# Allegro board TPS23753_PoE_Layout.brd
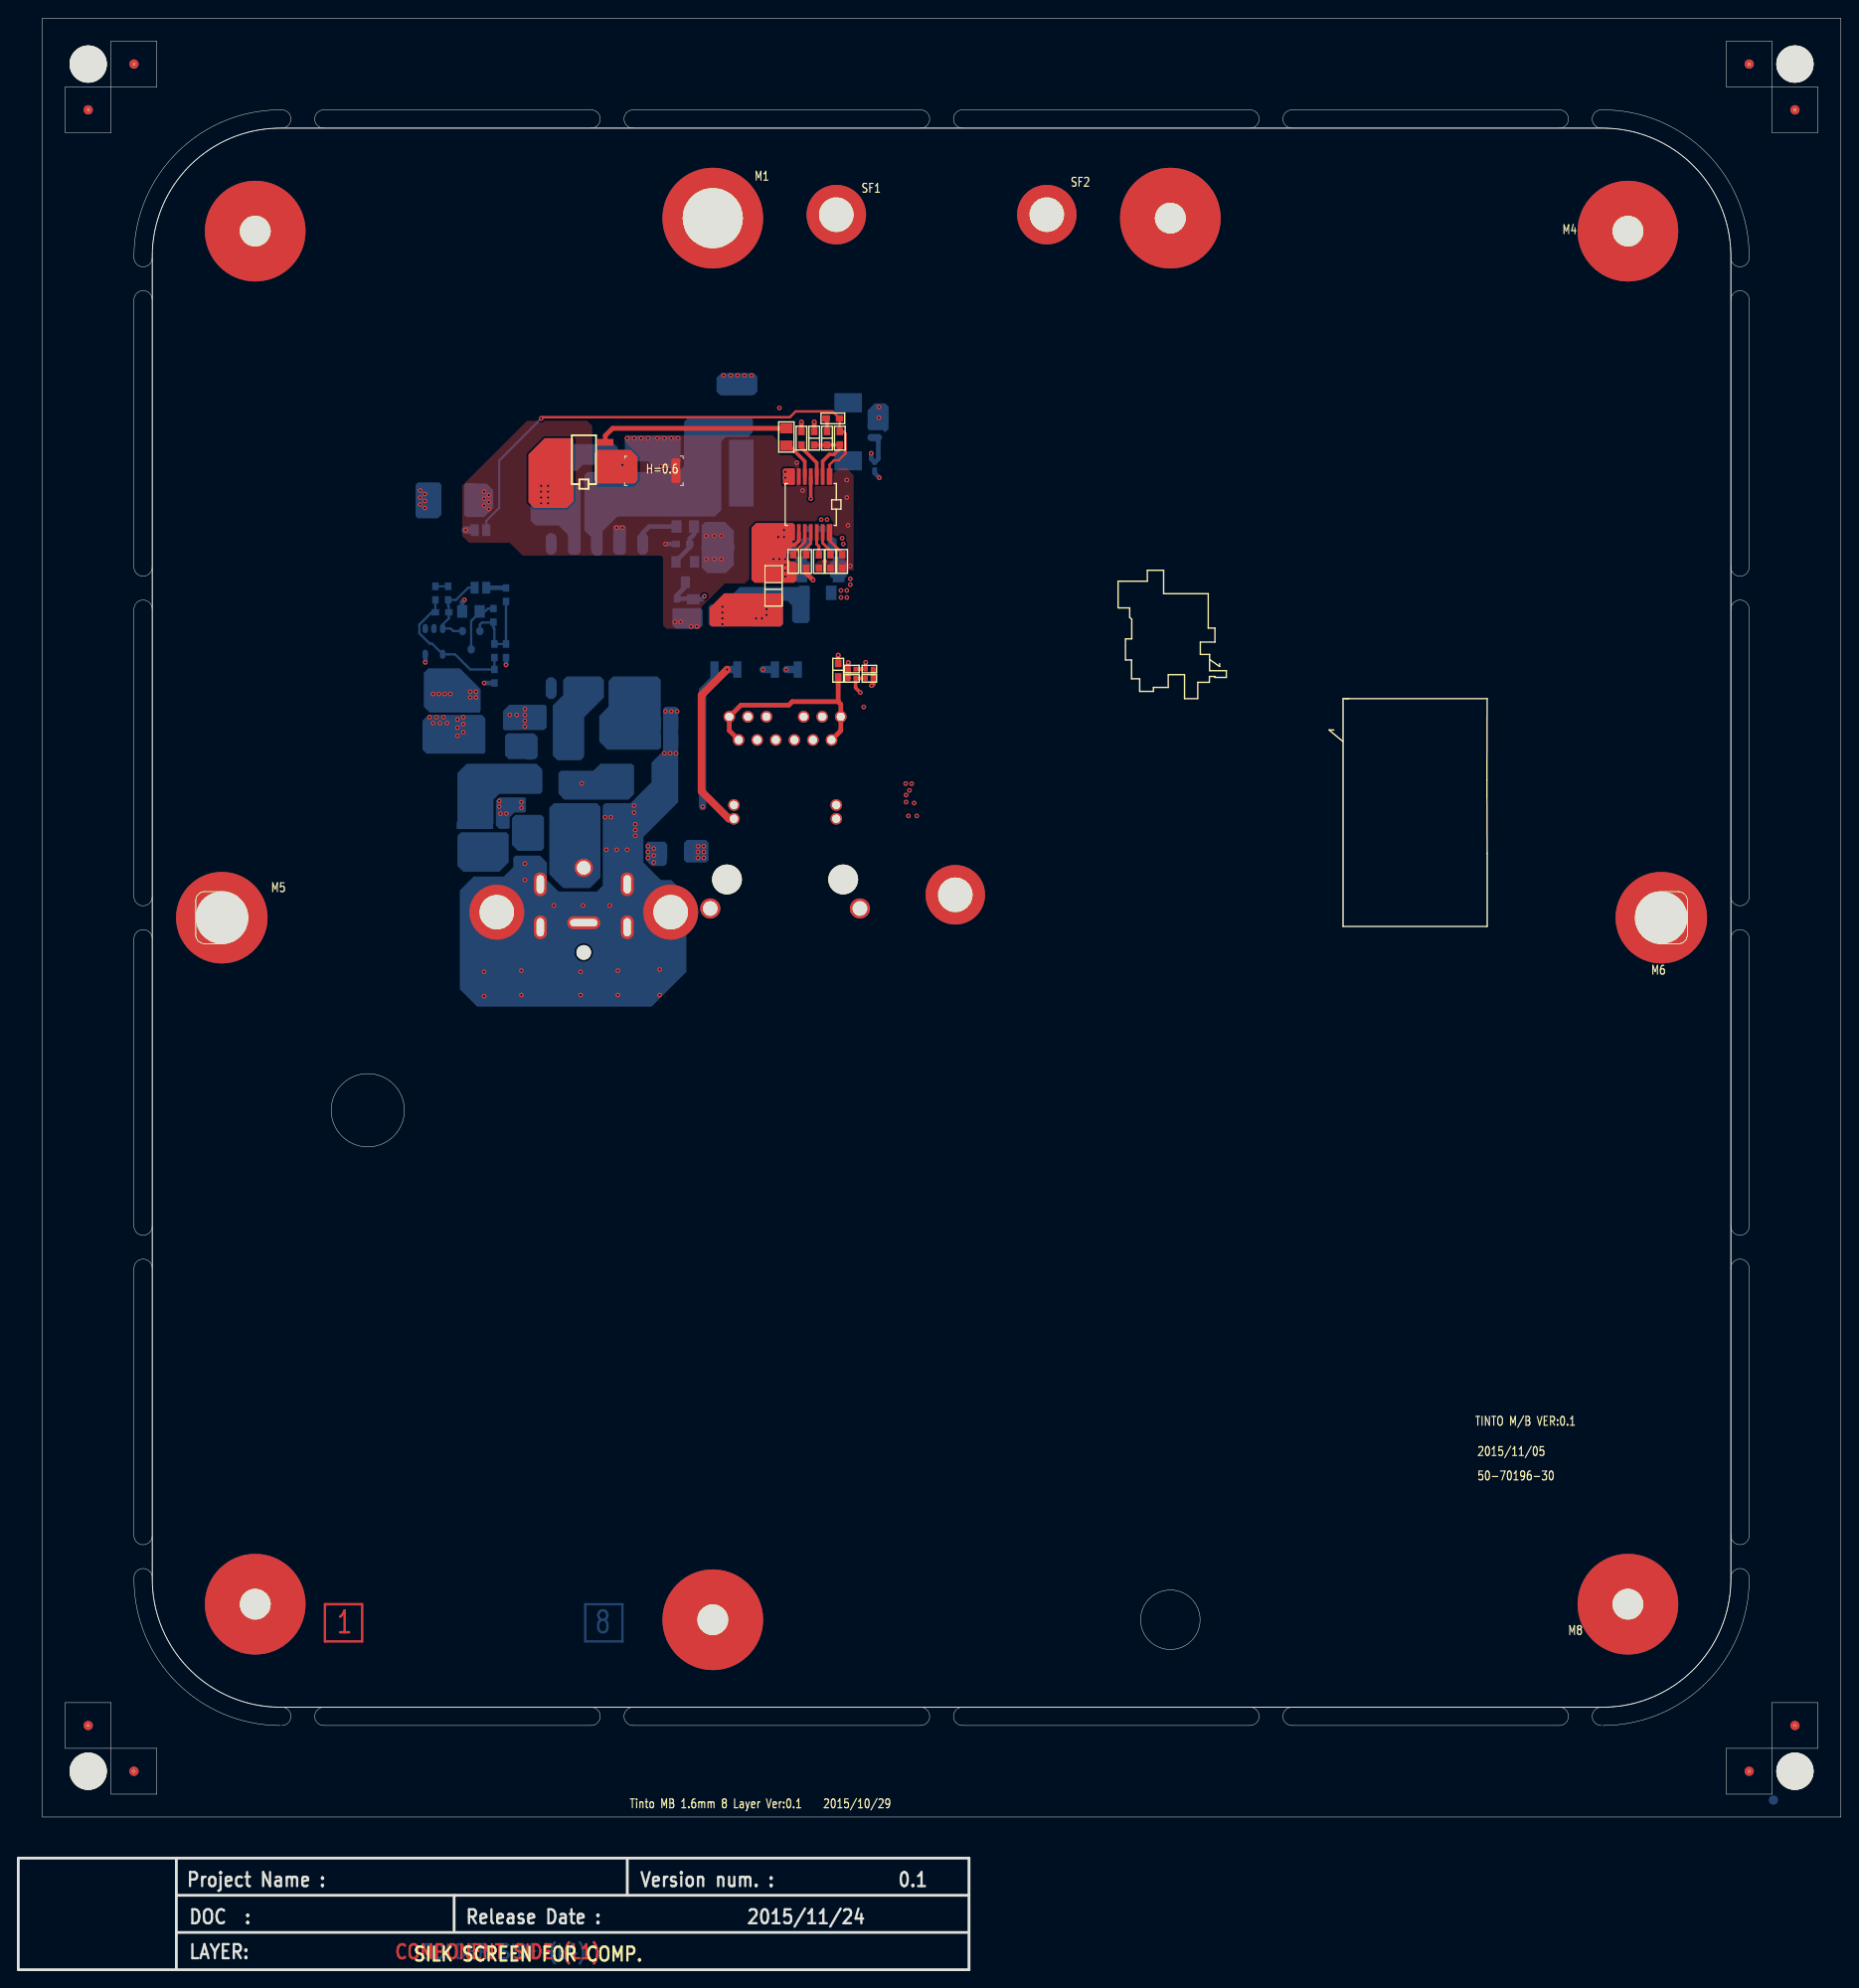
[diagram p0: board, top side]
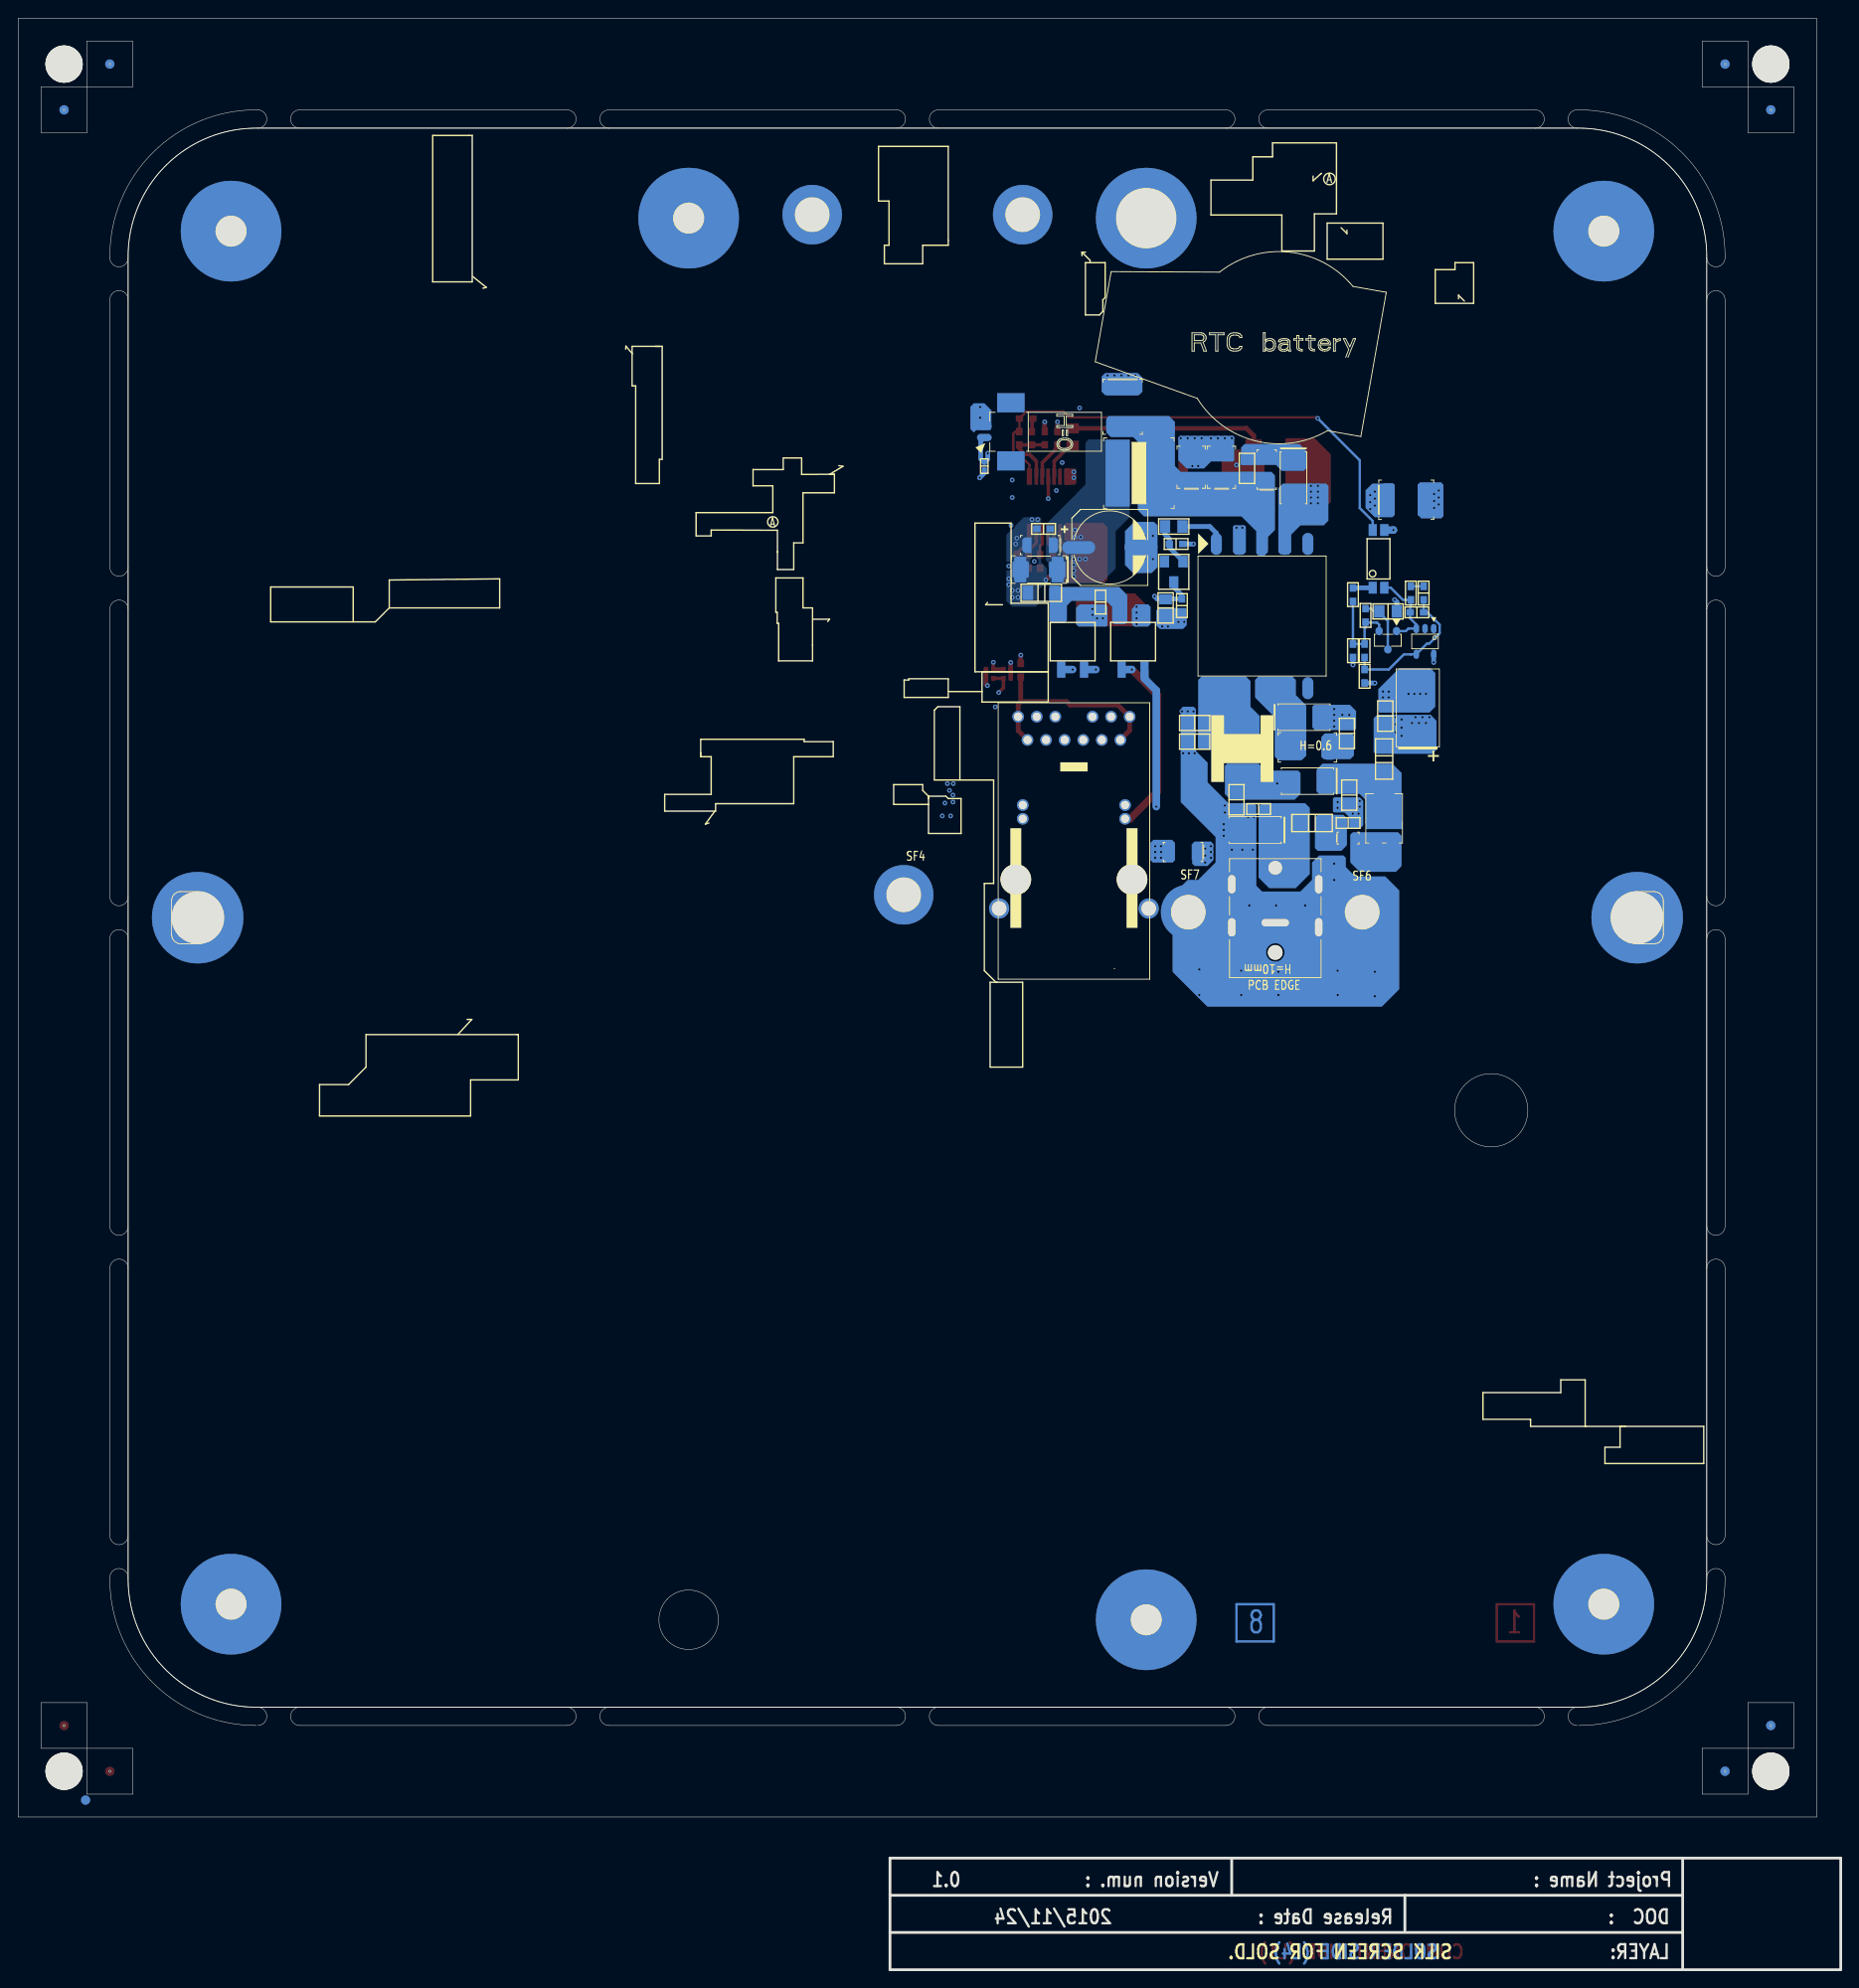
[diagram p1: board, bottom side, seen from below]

Outline 199.14 x 213.18 mm; copper layers: TOP, GND1, IN1, VCC1, VCC2, IN2, GND2, BOTTOM. Coordinates in mm from the lower left corner of the outline.
Outline path: circle c38.19,93.89 r4 ; circle c125.89,38.23 r3.25 ; 17.27,12.19 17.27,0 ; 17.27,8.13 103.89,8.13 ; 17.27,4.06 103.89,4.06 ; 47.62,8.13 47.62,4.32 ; 66.55,12.19 66.55,8.13 ; 0,12.19 0,0 103.89,0 103.89,12.19 0,12.19 ; 19.39,116.78 19.39,113.08 arc(19.68,112.37) 20.39,112.08 22.24,112.08 arc(25.09,114.93) 22.24,117.78 20.39,117.78 arc(19.68,117.49) 19.39,116.78 ; 179.54,112.08 arc(176.69,114.93) 179.54,117.78 181.39,117.78 arc(182.09,117.49) 182.39,116.78 182.39,113.08 arc(182.09,112.37) 181.39,112.08 179.54,112.08

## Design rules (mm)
constraint set DEFAULT: min track width 0.102
net group 50OHM-4(4.5): nets EMMC_CLK EMMC_CMD
net group GTX_CLK: nets GTX_CLK RGMII_TXCLK
net group LVDS1_CLK: nets LVDS1_CLK_N LVDS1_CLK_P
net group LVDS1_TX0: nets LVDS1_TX0_N LVDS1_TX0_P
net group LVDS1_TX1: nets LVDS1_TX1_N LVDS1_TX1_P
net group LVDS1_TX2: nets LVDS1_TX2_N LVDS1_TX2_P
net group LVDS1_TX3: nets LVDS1_TX3_N LVDS1_TX3_P
net group PHY_RST: nets PHY_RST RGMII_NRST
net group PHY_RX_CLK: nets PHY_RX_CLK RGMII_RXCLK
net group PWR-8: nets VDDHIGH_IN VDDHIGH_VPH
net group PWR-16: nets GEN_1V8 VGEN4_1V8
net group SD3_CLK: nets SD3_CLK SD_CLK_CN
net group SD3_CMD: nets SD3_CMD SD_CMD_CN
net group SD3_DATA0: nets SD3_DATA0 SD_DAT0_CN
net group SD3_DATA1: nets SD3_DATA1 SD_DAT1_CN
net group SD3_DATA2: nets SD3_DATA2 SD_DAT2_CN
net group SD3_DATA3: nets SD3_DATA3 SD_DAT3_CN
net group SD4_DA0: nets SD4_DA0 SD4_DATA0
net group SD4_DA1: nets SD4_DA1 SD4_DATA1
net group SD4_DA2: nets SD4_DA2 SD4_DATA2
net group SD4_DA3: nets SD4_DA3 SD4_DATA3
net group SD4_DA4: nets SD4_DA4 SD4_DATA4
net group SD4_DA5: nets SD4_DA5 SD4_DATA5
net group SD4_DA6: nets SD4_DA6 SD4_DATA6
net group SD4_DA7: nets SD4_DA7 SD4_DATA7
net group AUD3: nets AUD3_RXD AUD3_TXC AUD3_TXD AUD3_TXFS
net group CLK-20: nets CLK1_N CLK1_P CLK1_P_N CLK1_P_R
net group DDR_CLK: nets DRAM_SDCLK0 DRAM_SDCLK0_B DRAM_SDCLK1_B
net group DDR_CMD: nets DRAM_A0 DRAM_A1 DRAM_A2 DRAM_A3 DRAM_A4 DRAM_A5 DRAM_A6 DRAM_A7 DRAM_A8 DRAM_A9 DRAM_A10 DRAM_A11 DRAM_A12 DRAM_A13 DRAM_A14 DRAM_A15 DRAM_CAS_B DRAM_RAS_B DRAM_SDBA0 DRAM_SDBA1 DRAM_SDBA2 DRAM_WE_B
net group DDR_CTL: nets DRAM_CS0_B DRAM_CS1_B DRAM_SDCKE0 DRAM_SDCKE1 DRAM_SDODT0 DRAM_SDODT1
net group DDR_DATA0: nets DRAM_D0 DRAM_D4 DRAM_D7 DRAM_DQM0
net group DDR_DATA1: nets DRAM_D8 DRAM_D9 DRAM_D10 DRAM_D13 DRAM_DQM1
net group DDR_DATA2: nets DRAM_D16 DRAM_D17 DRAM_D20 DRAM_DQM2
net group DDR_DATA3: nets DRAM_D24 DRAM_D29 DRAM_DQM3
net group DDR_DQS: nets DRAM_SDQS0 DRAM_SDQS0_B DRAM_SDQS1 DRAM_SDQS1_B DRAM_SDQS2 DRAM_SDQS2_B DRAM_SDQS3 DRAM_SDQS3_B
net group DDR_OT: nets DRAM_RESET_B
net group EMMC_CLK: nets SD4_CLK
net group EMMC_CMD: nets SD4_CMD
net group GND: nets GND
net group I2C: nets I2C1_SCL I2C1_SDA I2C2_SCL I2C2_SDA I2C3_SCL I2C3_SDA PMIC_SCL PMIC_SDA
net group LVDS: nets LCD_CLK_N LCD_CLK_P LCD_TX0_N LCD_TX0_P LCD_TX1_N LCD_TX1_P LCD_TX2_N LCD_TX2_P LCD_TX3_N LCD_TX3_P
net group LVDS_3W-S11.4(12): nets LVDS0_CLK_N LVDS0_CLK_P LVDS0_TX0_N LVDS0_TX0_P LVDS0_TX1_N LVDS0_TX1_P LVDS0_TX2_N LVDS0_TX2_P LVDS0_TX3_N LVDS0_TX3_P
net group PWR: nets 2V5_RGMII 5VDDM DDR_1V5_L DDR_VREF DVDDL_RGMII EMMC_VDD ETH_RBIAS ETH_VDDIO_REG GEN_3V3_IN GEN_3V3_PMIC LAN_AVDD33 LAN_AVDDL LAN_DVDD_SW LCD_AVDD LCD_BL+ LCD_BL- LCD_PWM LCD_SUP LCD_VCOM LCD_VCOM_IN LCD_VDD LCD_VGH LCD_VGL LVDS_2V5 N2030210 N17702392 N18409851 N19092772 N19097147 N24036489 N24124655 N24230966 N24230987 N24253285 NFC_PVDD NFC_SIMVCC NFC_SVDD NFC_VBAT NVCC_CSI NVCC_EIM NVCC_MIPI NVCC_RGMII NVCC_SD1 NVCC_SD2 PCIE_VP PMIC_VCORE PMIC_VCOREREF PMIC_VDDOTP PMIC_VSNVS RTC_3V SATA_VP SENSOR_3V3 SENSOR_5V SET_1V8 SET_3V3 SW1CLX SYS_3V SYS_5V USB_H1_VBUS USB_OTG_VBUS VCCRTC VCOREDIG VDD5V_IN VDD_SNVS_CAP VDDCORE_R VDDSOC_R VGEN1_1V5 VGEN6_3V3 VOUT_1V8 VOUT_3V3 WLAN_3VIN
net group PWR-10: nets RF_ANT1 RF_ANT1_CN RF_ANT2 RF_ANT2_CN
net group PWR-12: nets NFC_1.8VDDM NFC_3VDDM NVCC_PLL_LDO NVCC_PLL_OUT
net group PWR-20: nets ETH_3V3 GEN_3V3 HDMI_VP N22820015 N24165639 N27686456 N27686764 NVCC_3V3 OTG_VBUS PA_3V3 VDD12V_POE VDD_IO VGEN2_1V5
net group PWR-40: nets AUX_3V15
net group PWR-80: nets VDDPU VDDSOC VDDSOC_CAP
net group PWR-100: nets DDR_1V5 VDD13_12 VDD_ARM_CAP VDDCORE
net group PWR-240: nets PMU3V
net group PWR-W6: nets GEN_2V5 HDMI_VPH PCIE_VPH SATA_VPH VGEN5_2V8 VSNVS_3V0
net group PWR-W32: nets PMIC_5V POE_VDD_CN POE_VSS_CN VDD_PSE_M1 VDD_PSE_M2 VDD_PSE_P1 VDD_PSE_P2
net group PWR_GATE: nets 3V_SW 5V_SW GEN_3V3_SW N17701522 N18409953 N39184104 N39184195 N39184527 N39184670 SW1LX SW3LX SW4LX SW_T
net group RGMII: nets RGMII_MDC RGMII_MDIO RGMII_RXD0 RGMII_RXD1 RGMII_RXD2 RGMII_RXD3 RGMII_RXDV RGMII_TXD0 RGMII_TXD1 RGMII_TXD2 RGMII_TXD3 RGMII_TXEN
net group S-10: nets G_LED_FB1 G_LED_FB2 G_LED_FB3 G_LED_FB4 G_LED_FB5 LED_G_POWER LED_GREEN LED_R_POWER LED_RED LED_YELLOW N17701582 N17701584 N17701586 N17701588 N17701590 N17701592 N17701594 N17701596 N17701598 N17701600 N17701602 N17701604 N17701700 N17701702 N17701704 N17701706 N17702195 N17702197 N17702222 N17702224 N17702236 N17702240 N17702242 N17702244 N17702269 N17702271 N17702317 N17702327 N17702414 N17702416 N17702418 N17702420 N17702422 N17702424 N17702426 N17702428 N17702430 N17702432 N17702434 N17702436 N17702438 N17702440 N17702495 N17702497 N17702499 N17702501 N17702503 N17702505 N17702507 N17702509 N17702511 N17702513 N17702515 N17702517 N17702581 N17702583 N17736265 N17736966 N17737669 N17738374 N17739081 N17739790 N17740501 N17741214 N17741929 N17742646 N17743365 N17744086 N17744809 N17745534 R_LED_IFB1 R_LED_IFB2 R_LED_IFB3 R_LED_IFB4 R_LED_IFB5 RGMII_LED_10_100 RGMII_LED_1000 RGMII_LED_ACT
net group S-20: nets N25586908 N28364944 N28380123
net group S_2W-S8(9): nets UART5_CTS UART5_RTS UART5_RXD UART5_TXD
net group SD: nets SD2_CD_B SD2_DATA4 SD2_DATA5 SD2_DATA6 SD2_DATA7 SD2_WP SD3_CD_B SD3_DATA4 SD3_DATA5 SD3_DATA6 SD3_DATA7 SD3_WP SD_CD#_CN
net group UART: nets UART1_RX UART1_RX_CN UART1_TX UART1_TX_CN UART3_RXD UART3_TXD
net group UART5: nets BT_CTS BT_RTS BT_RXD BT_TXD
net group USB: nets USB_HOST_DN USB_HOST_DP USB_OTG_DN USB_OTG_DP
net group XTAL: nets N27686566 N27686641 N27686643 N27686649 PHY_XTLI PHY_XTLO RTC_XTALI RTC_XTALO XTAL24_IN XTAL24_OUT

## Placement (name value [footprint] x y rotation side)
C27  -  [C0603]  86.97 167.31 90 top
C28  0.033uF  [C0603]  88.37 167.31 90 top
C49  2200pF  [C1812]  47.48 160.58 180 bottom
C153  0.1uF  [C0603]  89.59 141.96 270 top
C209  0.1UF  [C0402]  93.58 164.26 90 bottom
C233  2200pF  [C1812]  78.47 170.74 270 bottom
C248  -  [C1210]  67.67 164.13 0 bottom
C249  -  [C1210]  70.97 164.13 0 bottom
C250  -  [C1206]  62.72 163.88 0 bottom
C258  -  [CE_W830H830]  79.86 155.37 270 bottom
C259  -  [C0603]  72.62 155.75 180 bottom
C264  6800pF  [C0603]  45.57 150.39 270 bottom
C273  -  [C1206]  87.48 155.63 270 bottom
C275  0.22uF  [C0603]  71.99 149.02 270 bottom
C276  10pF  [C0603]  46.31 148.28 180 bottom
C278  -  [C0805]  73.77 148.77 270 bottom
C283  -  [C0805]  49.46 148.39 180 bottom
C288  -  [C0805]  70.59 136.19 0 bottom
C291  -  [C0805]  70.59 134.16 0 bottom
C292  -  [C0805]  53.95 135.05 90 bottom
C309  -  [C0805]  53.7 128.32 270 bottom
C313  -  [C0805]  66.02 127.81 270 bottom
C318  0.1uF  [C0603]  53.83 125.27 180 bottom
C320  -  [C7343]  46.21 137.85 90 bottom
C322  0.1uF  [C0603]  63.61 126.8 0 bottom
C323  -  [C0805]  49.76 136.96 90 bottom
C325  1000pF  [C1206]  71.86 122.1 270 bottom
C405  -  [C0603]  80.88 149.4 90 bottom
C406  -  [C0603]  87.1 157.4 0 bottom
CN2  -  [85204-0200]  93.58 167.38 270 bottom
CN3  -  [RJ45_16P_2PAD_RT5-3030T22Q]  83.79 119.1 0 bottom
CN5  -  [DCJACK_2DC-G213-B28]  61.79 114.38 0 bottom
D9  -  [DIODE_SMA]  59.8 162.99 270 bottom
D10  -  [SOT23_123]  72.88 152.7 270 bottom
D11  -  [DIODE_SMA-L]  87.61 152.96 0 bottom
D12  BAV99  [SOT_23-NPNP]  49.49 145.24 270 bottom
D13  -  [DIODE_SMA]  58.65 136.83 180 bottom
D14  -  [DIODE_MDI-H2_7]  77.32 145.08 90 bottom
D15  -  [DIODE_MDI-H2_7]  83.93 145.08 90 bottom
D16  -  [DIODE_SMA]  58.27 129.84 0 bottom
D17  -  [DIODE_POWERDI_3]  49.89 125.78 180 bottom
D18  -  [DIODE_SMA]  63.99 124.51 0 bottom
FB9  UPB321611T-121Y-N  [L1206]  82.53 151.18 90 top
FB10  UPB321611T-121Y-N  [L1206]  87.36 150.42 0 bottom
FB13  UPB321611T-121Y-N  [L1206]  57.76 125.27 180 bottom
FB14  UPB321611T-121Y-N  [L1206]  49.89 132.26 90 bottom
FS1  -  [PPTC0603]  53.83 123.62 90 bottom
L10  -  [L_CHOKE_670X670_CDRH6D28]  76.69 163.5 270 bottom
L12  -  [L_CHOKE_650X730-R185_350]  65.38 133.4 270 bottom
M1  -  [CTB1100Z700H650]  75.89 191.35 0 top
M2  -  [CTB1100Z380H330]  125.89 191.35 0 top
M3  -  [CTB1100Z380H330]  25.89 189.93 0 top
M4  -  [CTB1100Z380H330]  175.89 189.93 0 top
M5  -  [CTB1000Z620H570]  22.24 114.93 0 top
M6  -  [CTB1000Z620H570]  179.54 114.93 0 top
M7  -  [CTB1100Z380H330]  25.89 39.93 0 top
M8  -  [CTB1100Z380H330]  175.89 39.93 0 top
M10  -  [CTB1100Z380H330]  75.89 38.23 0 top
NOREF  -  []  25.89 39.93 0 top
NOREF#2  -  [unnamed#2]  7.64 21.68 0 top
NOREF#3  -  [unnamed#3]  7.64 203.18 0 top
NOREF#4  -  [unnamed#3]  12.64 21.68 0 top
NOREF#5  -  [unnamed#3]  7.64 26.68 0 top
NOREF#6  -  [unnamed#2]  194.14 21.68 0 top
NOREF#7  -  [unnamed#3]  194.14 203.18 0 top
NOREF#8  -  [unnamed#3]  25.89 39.93 0 top
NOREF#9  -  [unnamed#3]  12.64 208.18 0 top
NOREF#10  -  [unnamed#3]  189.14 208.18 0 top
NOREF#11  -  [unnamed#3]  189.14 21.68 0 top
NOREF#12  -  [unnamed#2]  194.14 208.18 0 top
NOREF#13  -  [unnamed#3]  194.14 26.68 0 top
NOREF#14  -  [unnamed#2]  7.64 208.18 0 top
NOREF#15  -  []  -0.13 -0.01 0 top
NOREF#16  -  [unnamed#3]  191.79 18.53 180 bottom
NOREF#17  -  [unnamed#3]  7.64 26.68 180 bottom
NOREF#18  -  [unnamed#3]  12.64 208.18 180 bottom
NOREF#19  -  [unnamed#3]  12.64 21.68 180 bottom
NOREF#20  -  [unnamed#3]  7.64 203.18 180 bottom
NOREF#21  -  [unnamed#3]  189.14 208.18 180 bottom
NOREF#22  -  [unnamed#3]  194.14 203.18 180 bottom
Q1  Si4848DY-T1  [SMD8A-184]  61.81 164.96 90 top
R10  1.5K  [R0603]  89.01 169.47 0 top
R11  -  [R0603]  85.58 167.31 270 top
R16  -  [R0805]  83.93 167.44 90 top
R17  2K  [R0603]  89.77 167.31 90 top
R20  0.39  [R2010]  69.45 163.75 0 top
R48  80.6K  [R0603]  88.75 153.85 270 top
R49  59K  [R0603]  90.02 153.85 270 top
R54  -  [R0603]  84.69 153.85 90 top
R55  -  [R0603]  86.09 153.85 90 top
R56  -  [R0603]  87.48 153.85 90 top
R92  10K  [R0402]  92.99 142.09 180 top
R93  10K  [R0402]  91.09 142.09 0 top
R94  10K  [R0402]  92.99 141.07 180 top
R96  10K  [R0402]  91.09 141.07 0 top
R172  -  [R0805]  64.88 164.01 90 bottom
R193  -  [R0805]  72.88 157.66 180 bottom
R208  -  [R0603]  46.97 150.39 90 bottom
R213  2K  [R0603]  53.3 150.21 90 bottom
R216  -  [R0603]  52.03 144.09 270 bottom
R217  -  [R0603]  53.3 144.09 90 bottom
R219  -  [R0603]  52.03 141.3 270 bottom
R236  -  [R0603]  51.92 147.95 90 bottom
R243  -  [R2010]  58.27 133.53 180 bottom
SF1  -  [NUT_CT650BZ410H370]  89.39 191.73 0 top
SF2  -  [NUT_CT650BZ410H370]  112.39 191.73 0 top
SF4  -  [NUT_CT650BZ410H370]  102.39 117.43 180 bottom
SF6  -  [NUT_CTB600Z420H370]  52.29 115.53 180 bottom
SF7  -  [NUT_CTB600Z420H370]  71.29 115.53 180 bottom
T1  -  [TRANSFOMER_10_W1400L1765P250]  63.23 147.88 0 bottom
U4  TPS23753PWR  [TSSOP14__65M_240-H1_2]  86.59 160.07 180 top
U22  TCMT1107  [SOP4_1_27M]  50.5 154.13 180 bottom
U25  TL431ACDBVR  [SOT_23_5-H1_45]  45.42 145.11 270 bottom

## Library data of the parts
C27 = 10-52868-00
C28 = 10-51208-00
C49 C233 = 10-51542-00
C153 C318 C322 = 10-52979-00
C209 = 10-53021-00
C248 C249 = 10-51642-00
C250 C273 = 10-51546-00
C258 = 10-30880-01
C259 C405 C406 = 10-51643-00
C264 = 10-51177-00
C275 = 10-52872-00
C276 = 10-51452-00
C278 = 10-51639-00
C283 C323 = 10-51372-00
C288 C291 C309 C313 = 10-51616-00
C292 = 10-51448-00
C320 = 10-40806-01
C325 = 10-51179-00
CN2 = 20-20294-20
CN3 = 20-26663-01
CN5 = 20-26641-01
D9 = 06-10840-02
D10 = 06-10588-02
D11 = 06-10836-01
D12 = 06-10571-05
D13 D16 = 06-10873-01
D14 D15 = 06-10963-01
D17 = 06-10944-01
D18 = 06-10961-01
FB9 FB10 FB13 FB14 = 21-92453-01
FS1 = 21-10724-02
L10 = 12-00911-01
L12 = 12-01952-02
M1 = CTB1100Z700H650
M2-M4 M7 M8 M10 = CTB1100Z380H330
M5 M6 = CTB1000Z620H570
Q1 = 06-24124-01
R10 = 11-14720-00
R11 = 11-14244-00
R16 R193 = 11-13582-00
R17 R213 = 11-14267-00
R20 = 11-13374-00
R48 = 11-14393-00
R49 = 11-13067-00
R54 = 11-14539-00
R55 = 11-12938-00
R56 R208 R236 = 11-14280-00
R92 R94 = NU_11-14297-00
R93 R96 = 11-14297-00
R172 = 11-13581-00
R216 = 11-13568-00
R217 = 11-14214-00
R219 = 11-13338-00
R243 = 11-13504-00
SF1 SF2 = 24-12459-00
SF4 = 24-12460-00
SF6 SF7 = 24-12194-00
T1 = 12-02504-01
U4 = 05-32472-01
U22 = 05-32471-01
U25 = 05-32473-01

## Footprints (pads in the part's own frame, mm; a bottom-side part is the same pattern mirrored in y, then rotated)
85204-0200
  oval 0.8x1.6 smd: 1(0,0) 2(-1.25,0)
  rect 2.1x3 smd: PAD1(2.55,2.9) PAD2(-3.8,2.9)
C0402
  rect 0.457x0.508 smd: 1(-0.4,0) 2(0.4,0)
C0603
  rect 0.813x0.711 smd: 1(-0.737,0) 2(0.737,0)
C0805
  rect 1.118x1.372 smd: 1(-0.95,0) 2(0.95,0)
C1206
  custom 0.25x0.25 smd: 1(0,1.45) 2(0,-1.45)
C1210
  custom 0.35x0.35 smd: 1(0,1.4) 2(0,-1.4)
C1812
  custom 0.35x0.35 smd: 1(-1.95,0) 2(1.95,0)
C7343
  custom 0.475x0.475 smd: 1(-3.1,0) 2(3.1,0)
CE_W830H830
  oval 1.4x3.6 smd: 1(0,-3.4) 2(0,3.4)
CTB1000Z620H570
  round 10 hole 5.7: 1(0,0)
CTB1100Z380H330
  round 11 hole 3.3: 1(0,0)
CTB1100Z700H650
  round 11 hole 6.5: 1(0,0)
DCJACK_2DC-G213-B28
  round 1.6 hole 1.6 unplated: (0,3.25)
  round 2 hole 1.5: 1(0,-6)
  oval 3.6x1.4 hole 3x0.8: 2(0,0)
  oval 1.4x2.6 hole 0.8x2: PAD1(-4.75,0.5) PAD2(4.75,0.5) PAD3(-4.75,-4.2) PAD4(4.75,-4.2)
DIODE_MDI-H2_7
  rect 1.803x0.889 smd: 1(3.048,-1.25) 2(3.048,1.25) 3(-3.048,1.25) 4(-3.048,-1.25)
DIODE_POWERDI_3
  custom 0.275x0.275 smd: A1(-0.92,-2.9) A2(0.92,-2.9)
  custom 1x1 smd: C(0,1.05)
DIODE_SMA
  rect 1.8x2.2 smd: A(1.95,0) C(-1.95,0)
DIODE_SMA-L
  custom 0.45x0.45 smd: A(2,0) C(-2,0)
L1206
  rect 1.168x1.575 smd: 1(-1.473,0) 2(1.473,0)
L_CHOKE_650X730-R185_350
  rect 1.85x3.5 smd: 1(-2.775,0) 2(2.775,0)
L_CHOKE_670X670_CDRH6D28
  rect 7.3x2.65 smd: 1(0,-2.325) 2(0,2.325)
NUT_CT650BZ410H370
  round 6.5 hole 3.7: 1(0,0)
NUT_CTB600Z420H370
  round 6 hole 3.7: 1(0,0)
PPTC0603
  custom 0.15x0.15 smd: 1(0,0.7) 2(0,-0.7)
R0402
  rect 0.457x0.508 smd: 1(-0.4,0) 2(0.4,0)
R0603
  rect 0.813x0.711 smd: 1(-0.737,0) 2(0.737,0)
R0805
  rect 1.118x1.372 smd: 1(-0.95,0) 2(0.95,0)
R2010
  custom 0.25x0.25 smd: 1(-2.4,0) 2(2.4,0)
RJ45_16P_2PAD_RT5-3030T22Q
  round 3.25 hole 3.25 unplated: (-6.35,0) (6.35,0)
  round 1.27 hole 0.9: 1(-5.075,-15.24) 2(-3.045,-15.24) 3(-1.015,-15.24) 4(1.015,-15.24) 5(3.045,-15.24) 6(5.075,-15.24) 7(-6.09,-17.78) 8(-4.06,-17.78) 9(-2.03,-17.78) 10(2.03,-17.78) 11(4.06,-17.78) 12(6.09,-17.78) 13(-5.59,-8.13) 14(5.59,-8.13) 15(-5.59,-6.63) 16(5.59,-6.63)
  round 2.2 hole 1.6: PAD1(-8.175,3.17) PAD2(8.175,3.17)
SMD8A-184
  rect 0.711x1.778 smd: 1(-1.905,-2.34) 2(-0.635,-2.34) 3(0.635,-2.34) 4(1.905,-2.34) 5(1.905,2.34) 6(0.635,2.34) 7(-0.635,2.34) 8(-1.905,2.34)
SOP4_1_27M
  rect 0.889x1.295 smd: 1(-0.635,-3.15) 2(0.635,-3.15) 3(0.635,3.15) 4(-0.635,3.15)
SOT23_123
  rect 1.27x1.016 smd: 1(-1.118,1.016) 2(-1.118,-1.016) 3(1.118,0)
SOT_23-NPNP
  oval 0.9x0.8 smd: N(-1,-0.95) NP(1,0) P(-1,0.95)
SOT_23_5-H1_45
  oval 1x0.6 smd: 1(-1.4,0.95) 2(-1.4,0) 3(-1.4,-0.95) 4(1.4,-0.95) 5(1.4,0.95)
TRANSFOMER_10_W1400L1765P250
  oval 1.2x2.4 smd: 1(5,-7.88) 2(2.5,-7.88) 3(0,-7.88) 4(-2.5,-7.88) 5(-5,-7.88) 6(-5,7.88) 7(-2.5,7.88) 8(0,7.88) 9(2.5,7.88) 10(5,7.88)
TSSOP14__65M_240-H1_2
  rect 0.61x1.778 smd: 1(-2.052,-3.048) 7(2.052,-3.048) 8(2.052,3.048) 14(-2.052,3.048)
  rect 0.406x1.778 smd: 2(-1.3,-3.048) 3(-0.65,-3.048) 4(0,-3.048) 5(0.65,-3.048) 6(1.3,-3.048) 9(1.3,3.048) 10(0.65,3.048) 11(0,3.048) 12(-0.65,3.048) 13(-1.3,3.048)
unnamed#2
  round 4.064 hole 4.064 unplated: (0,0)
unnamed#3
  round 1.016 smd: 1(0,0)

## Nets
2V5_RGMII: R92.1(TP-1) R94.1(TP-1)
GND: C49.2 C153.1(TP-1) C209.1(TP-1) C233.1 C283.2 C288.2 C291.2 C292.2 C309.2 C313.2 C318.2(TP-2) C320.2 C322.2(TP-2) C323.2 C325.1(TP-1) CN2.2 CN5.2 CN5.PAD1 CN5.PAD2 CN5.PAD3 CN5.PAD4 D13.A D18.A M1.1 M2.1 M3.1 M4.1 M5.1 M6.1 M7.1 M8.1 M10.1 R93.1(TP-1) R96.1(TP-1) R219.2 SF1.1 SF2.1 SF4.1 SF6.1 SF7.1 U25.5
VCCRTC: C209.2(TP-2) CN2.1
VDD12V_POE: C313.1 D16.A L12.2 R217.1(TP-1)
VDD13_12: C320.1 C323.1 FB14.2
VDD_PSE_M1: CN3.14 D15.4
VDD_PSE_M2: CN3.16 D14.4
VDD_PSE_P1: CN3.13 D15.3
VDD_PSE_P2: CN3.15 D14.3
GLH: C325.2(TP-2) CN3.PAD1 CN3.PAD2
POE_ADP: R56.2(TP-2) U4.12
POE_CTL: R10.2(TP-2) R17.2(TP-2) U4.1 U22.4
POE_PRI_SW_NODE: D9.A Q1.5 Q1.6 Q1.7 Q1.8 T1.4
POE_RTN: C27.2 C49.1 C248.2 C249.2 C258.2 C259.2 C275.2(TP-2) C278.2 R20.2 R48.2(TP-2) R49.2(TP-2) R56.1(TP-1) T1.2 U4.6 U22.3
POE_VB: C27.1 C28.1(TP-1) R17.1(TP-1) U4.2
POE_VDD: C258.1 C273.1 C406.1 D11.C FB9.2 L10.1 R54.1 U4.8 U4.9
POE_VDD_CN: C405.1 D14.1 D15.1 FB9.1
POE_VSS: C273.2 C406.2 D11.A FB10.2 R55.1(TP-1) U4.7
POE_VSS_CN: C405.2 D14.2 D15.2 FB10.1
RGMII_LED_1000: R94.2(TP-2) R96.2(TP-2)
RGMII_LED_ACT: R92.2(TP-2) R93.2(TP-2)
RGMII_TRXN0: CN3.10
RGMII_TRXN1: CN3.5
RGMII_TRXN2: CN3.2
RGMII_TRXN3: CN3.9
RGMII_TRXP0: CN3.11
RGMII_TRXP1: CN3.4
RGMII_TRXP2: CN3.3
RGMII_TRXP3: CN3.8
N25585706: C264.2(TP-2) C276.2(TP-2) R216.2 R219.1 U25.4
N25585768: R193.2 T1.1
N25585770: C276.1(TP-1) D12.P R208.1(TP-1) U22.2 U25.3
N25585804: C275.1(TP-1) C278.1 D10.3 U4.4
N25585918: C250.2 D9.C R172.2
N25586716: D12.N R213.1(TP-1) R216.1 R217.2(TP-2) R236.1(TP-1)
N25586736: C259.1 D10.1 R193.1
N25586772: R48.1(TP-1) U4.13
N25586778: R49.1(TP-1) U4.14
N25586811: R213.2(TP-2) U22.1
N25586821: R11.2 U4.3
N25586882: C288.1 C291.1 L12.1 T1.9 T1.10
N25586908: Q1.4 R16.2
N25586910: Q1.1 Q1.2 Q1.3 R11.1 R20.1
N25587015: D13.C R243.1 T1.7 T1.8
N25587065: C233.2 C248.1 C249.1 C250.1 L10.2 R172.1 T1.3
N25587094: R54.2 U4.10
N25587194: C264.1(TP-1) R208.2(TP-2)
N25587240: C283.1 D12.NP R236.2(TP-2)
N25587378: R55.2(TP-2) U4.11
N25587545: R16.1 U4.5
N25594365: C153.2(TP-2) CN3.1 CN3.6 CN3.7 CN3.12
N25600625: C322.1(TP-1) CN5.1 D18.C FB13.1
N25600639: D17.A1 D17.A2 FS1.2
N25600655: C309.1 D16.C D17.C FB14.1
N25600703: C318.1(TP-1) FB13.2 FS1.1
N25856521: C292.1 R243.2
N26013479: C28.2(TP-2) R10.1(TP-1)

Pads without a net: CN2 PAD1 PAD2; D10 2; NOREF#3 1; NOREF#4 1; NOREF#5 1; NOREF#7 1; NOREF#8 1; NOREF#9 1; NOREF#10 1; NOREF#11 1; NOREF#13 1; NOREF#16 1; NOREF#17 1; NOREF#18 1; NOREF#19 1; NOREF#20 1; NOREF#21 1; NOREF#22 1; T1 5 6; U25 1 2

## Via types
v1: diameter 0.508, hole 0.254, TOP to BOTTOM, 195 vias

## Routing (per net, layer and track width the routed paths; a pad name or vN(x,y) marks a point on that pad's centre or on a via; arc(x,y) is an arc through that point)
2V5_RGMII: length 1.9
  TOP w0.508: v1(93.24,140.28) 93.39,140.43 R94.1 R92.1
GND: length 7.1
  TOP w0.508: v1(90.69,142.8) R93.1 R96.1 ; C153.1 v1(89.59,143.61)
  BOTTOM w0.508: C209.1 93.58,163.5 v1(94.09,162.99) ; R219.2 v1(50.91,140.56) ; C283.2 48.49,148.4 48.49,149.4 v1(48.75,149.66) ; U25.5 v1(44.47,142.82)
  vias: v1(43.92,161.59) v1(43.92,160.83) v1(43.92,160.07) v1(44.43,161.21) v1(44.43,160.45) v1(44.43,159.69) v1(45.32,139.37) v1(45.95,139.37) v1(46.59,139.37) v1(47.22,139.37) v1(49.38,139.62) v1(49.38,138.99) v1(50.02,139.62) v1(50.02,138.99) v1(50.91,109.02) v1(50.91,106.35) v1(52.56,127.69) v1(52.56,127.05) v1(52.68,126.29) v1(53.32,126.29) v1(53.7,137.08) v1(54.46,137.08) v1(54.97,127.56) v1(54.97,126.92) v1(54.97,109.14) v1(54.97,106.48) v1(55.35,137.72) v1(55.35,137.08) v1(55.35,136.45) v1(55.35,135.81) v1(55.35,120.83) v1(55.35,119.05) v1(58.53,116.26) v1(61.45,109.02) v1(61.45,106.48) v1(61.7,116.26) v1(64.11,125.91) v1(64.24,122.35) v1(64.62,116.26) v1(64.75,125.91) v1(65.38,122.35) v1(65.51,109.14) v1(65.51,106.48) v1(66.53,122.35) v1(67.29,127.18) v1(67.29,126.42) v1(67.42,125.15) v1(67.42,124.51) v1(67.42,123.88) v1(68.81,122.73) v1(68.81,122.1) v1(68.81,121.46) v1(69.45,122.48) v1(69.45,121.72) v1(69.45,120.95) v1(70.08,109.27) v1(70.08,106.48) v1(70.59,132.89) v1(70.72,137.46) v1(71.23,132.89) v1(71.35,137.46) v1(71.86,132.89) v1(71.99,137.46) v1(77.07,174.17) v1(77.83,174.17) v1(78.59,174.17) v1(79.35,174.17) v1(80.12,174.17) v1(94.04,170.71) v1(94.04,169.54) v1(97.39,128.83) v1(97.88,127.45)
VCCRTC: length 4.2
  BOTTOM w0.508: v1(93.2,165.66) 93.2,165.04 C209.2 93.98,165.06 93.98,166.98 CN2.1
VDD12V_POE: length 22.3
  IN1 w0.508: v1(53.29,142.54) 52.33,141.58 52.33,131.47 54.21,129.59 v1(61.57,129.59)
  BOTTOM w0.508: v1(53.29,142.54) 53.29,143.35 R217.1
VDD13_12:
  vias: v1(44.94,136.83) v1(45.32,136.19) v1(45.7,136.83) v1(46.08,136.19) v1(46.46,136.83) v1(46.84,136.19) v1(47.99,136.58) v1(47.99,135.69) v1(47.99,134.8) v1(48.62,136.83) v1(48.62,136.07) v1(48.62,135.18)
VDD_PSE_M1: length 32.9
  IN1 w0.762: CN3.14 82.04,127.23 79.18,130.1 76.51,130.1 74.66,131.95 74.66,138.86 76.94,141.15 80.5,141.15 v1(81.39,142.04)
  BOTTOM w0.813: v1(81.39,142.04) D15.4
VDD_PSE_M2: length 32
  IN1 w0.813: v1(74.78,127.05) 76.43,128.7 78.8,128.7 81.76,125.73 CN3.16
  BOTTOM w0.813: v1(74.78,127.05) 74.78,139.75 76.07,141.04 D14.4
VDD_PSE_P1: length 24.6
  IN2 w0.762: v1(83.93,142.04) 82.91,142.04 82.02,141.15 77.45,141.15 74.66,138.35 74.66,130.77 CN3.13
  BOTTOM w0.813: v1(83.93,142.04) D15.3
VDD_PSE_P2: length 20.4
  TOP w0.813: CN3.15 77.65,125.73 74.66,128.73 74.66,139.24 v1(77.45,142.04)
  BOTTOM w0.813: D14.3 v1(77.45,142.04)
ETH_3V3:
  vias: v1(96.97,129.58) v1(97.62,129.57)
GLH:
  vias: v1(74.27,122.73) v1(74.27,122.1) v1(74.27,121.46) v1(74.91,122.73) v1(74.91,122.1) v1(74.91,121.46)
POE_ADP: length 2.5
  TOP w0.305: R56.2 87.48,155.5 87.24,155.74 U4.12
POE_CTL: length 55.8
  TOP w0.254: v1(57.13,169.47) 57.26,169.6 84.31,169.6 84.94,170.23 88.98,170.23 R10.2 89.74,168.07 R17.2 90.15,168.05 90.4,167.79 90.4,165.66 89.64,164.9 89.13,164.9 88.65,164.41 U4.1
  BOTTOM w0.254: v1(57.13,169.47) 52.56,164.9 52.56,159.69 51.14,158.27 U22.4
POE_PRI_SW_NODE:
  vias: v1(57.13,162.1) v1(57.13,161.47) v1(57.13,160.83) v1(57.13,160.2) v1(57.89,162.1) v1(57.89,161.47) v1(57.89,160.83) v1(57.89,160.2)
POE_RTN: length 3.2
  TOP w0.508: C27.2 v1(86.97,169.09)
  BOTTOM w0.508: C259.2 v1(70.72,155.75)
  BOTTOM w0.813: v1(48.88,157.28) U22.3
  vias: v1(50.91,161.47) v1(50.91,160.71) v1(50.91,159.94) v1(51.41,161.09) v1(51.41,160.32) v1(51.41,159.56) v1(65.38,157.53) v1(66.02,157.53) v1(66.53,167.31) v1(67.29,167.31) v1(68.05,167.31) v1(68.81,167.31) v1(69.83,167.31) v1(70.21,164.26) v1(70.59,167.31) v1(70.85,164.26) v1(71.35,167.31) v1(71.73,147.24) v1(72.12,167.31) v1(72.37,147.24) v1(73.51,146.74) v1(74.15,146.74) v1(75.16,156.64) v1(75.16,154.1) v1(76.05,156.64) v1(76.05,154.1) v1(76.81,156.64) v1(76.81,154.1) v1(83.16,170.61) v1(85.07,164.64) v1(85.7,161.59) v1(88.12,153.85) v1(90.53,162.74) v1(90.53,160.83) v1(90.66,157.78) v1(90.91,153.34)
POE_VB: length 7.8
  TOP w0.381: C27.1 C28.1 88.12,166.57 89.64,166.57 R17.1 89.77,166.17 89.13,165.53 88.63,165.53 87.89,164.8 U4.2
POE_VDD: length 2.2
  TOP w0.381: U4.9 85.29,156.1 84.82,155.63 84.18,155.63
  vias: v1(82.53,154.1) v1(83.04,156.51) v1(83.16,154.1) v1(83.67,157.28) v1(83.67,156.51) v1(83.8,154.1) v1(83.8,153.47) v1(83.8,152.83) v1(83.8,152.2)
POE_VDD_CN:
  vias: v1(76.94,148.89) v1(76.94,148.26) v1(76.94,147.62) v1(76.94,146.99) v1(80.62,147.62) v1(81.26,147.62) v1(81.77,148.64) v1(81.77,148.01)
POE_VSS: length 1.6
  TOP w0.508: R55.1 86.09,152.58 v1(86.85,151.82)
  vias: v1(83.8,163.63) v1(83.8,162.99) v1(87.74,158.42) v1(88.37,158.42) v1(89.9,150.67) v1(89.9,149.91) v1(90.02,156.39) v1(90.15,155.75) v1(90.53,150.67) v1(90.53,149.91) v1(90.91,151.94) v1(90.91,151.31)
RGMII_LED_1000: length 2.9
  TOP w0.381: v1(92,139.52) 91.49,140.04 R96.2 R94.2
RGMII_LED_ACT: length 7
  TOP w0.381: v1(92.59,142.83) R92.2 R93.2
  IN1 w0.381: v1(92.59,142.83) 92.59,139.85 92.82,139.62 92.82,138.38 v1(92.39,137.95)
RGMII_TRXN0: length 24.1
  IN2 w0.102: CN3.10 86.51,136.88 86.75,136.64 86.75,136.26 86.24,135.76 84.5,135.76 83.66,134.92 83.66,133.14 85.96,130.83 90.86,130.83 95.01,126.68 97.45,126.68 97.59,126.54 97.59,126.37 v1(97.26,126.04)
RGMII_TRXN1: length 14.8
  IN2 w0.102: CN3.5 86.03,133.54 86.03,132.89 86.49,132.44 91.5,132.44 95.84,128.09 96.78,128.09 v1(97.01,128.32)
RGMII_TRXN2: length 20
  IN2 w0.102: CN3.2 81.41,134.34 81.58,134.52 81.58,135.21 82.28,135.9 82.83,135.9 84.95,138.02 90.38,138.02 95.1,133.29 96.5,133.29 96.74,133.53
RGMII_TRXN3: length 21.2
  IN2 w0.102: CN3.9 81.05,136.88 80.85,137.09 80.85,137.6 81.34,138.09 84.14,138.09 84.59,138.54 90.57,138.54 92.79,136.33 97.6,136.33 98.01,135.92 98.01,135.55 97.88,135.42 97.71,135.42 97.47,135.66
RGMII_TRXP0: length 24
  IN2 w0.102: CN3.11 87.27,136.88 87.05,136.67 87.05,136.14 86.37,135.45 84.62,135.45 83.96,134.79 83.96,133.26 86.09,131.14 90.99,131.14 95.14,126.99 97.58,126.99 97.9,126.67 97.9,126.32 v1(98.17,126.04)
RGMII_TRXP1: length 15.4
  IN2 w0.102: CN3.4 85.73,133.42 85.73,132.77 86.36,132.13 91.37,132.13 95.71,127.79 96.78,127.79 v1(97.01,127.56)
RGMII_TRXP2: length 19.5
  IN2 w0.102: CN3.3 82.03,134.34 81.89,134.48 81.89,135.08 82.4,135.6 82.96,135.6 85.07,137.72 90.25,137.72 94.98,132.99 96.52,132.99 96.74,132.77
RGMII_TRXP3: length 22.6
  IN2 w0.102: CN3.8 80.34,136.88 80.54,137.08 80.54,137.73 81.21,138.39 84.01,138.39 84.47,138.85 90.7,138.85 92.92,136.63 97.72,136.63 98.31,136.04 98.31,135.42 98,135.11 97.69,135.11 97.47,134.9
N25585706: length 15.8
  BOTTOM w0.254: C264.2 C276.2 45.17,148.28 43.82,146.94 43.82,146 44.96,144.87 45.21,144.87 U25.4 46.93,143.71 46.95,143.69 47.73,143.69 49.38,142.04 R219.1 R216.2
N25585768: length 5.2
  BOTTOM w0.508: T1.1 68.23,156.94 68.94,157.66 R193.2
N25585770: length 9.2
  BOTTOM w0.254: D12.P 47.52,146.24 47.25,146.51 U25.3 46.37,146.95 47.05,147.62 C276.1 47.05,148.88 46.97,148.96 R208.1 47.85,149.66 49.17,150.98 U22.2
N25585804: length 26.4
  TOP w0.381: v1(86.59,160.71) U4.4
  IN2 w0.508: v1(74.98,150.04) 77.96,153.02 77.96,157.53 81.13,160.71 v1(86.59,160.71)
  BOTTOM w0.508: D10.3 72.88,151.05 71.99,150.16 C275.1 73.73,149.76 C278.1 74.66,149.72 v1(74.98,150.04)
N25586716: length 10.6
  BOTTOM w0.254: D12.N 50.44,146.94 50.66,147.17 51.92,147.17 ; 51.92,147.17 51.92,146.61 52.03,146.5 R216.1 R217.2 R213.1 ; 51.92,147.17 R236.1
N25586736: length 4.6
  BOTTOM w0.508: R193.1 73.83,156.79 73.36,156.32 C259.1 73.36,155.37 71.86,153.87 D10.1
N25586772: length 2.8
  TOP w0.305: U4.13 87.89,155.85 88.75,154.99 R48.1
N25586778: length 3
  TOP w0.305: U4.14 88.65,156.13 90.02,154.76 R49.1
N25586811: length 2.2
  BOTTOM w0.508: U22.1 R213.2
N25586821: length 4.1
  TOP w0.381: U4.3 87.24,164.63 85.58,166.29 R11.2
N25586908: length 20.8
  TOP w0.508: Q1.4 64.15,167.6 64.94,168.39 R16.2
N25586910: length 22.5
  TOP w0.508: R11.1 v1(85.58,169.09)
  IN1 w0.508: v1(85.58,169.09) 83.16,166.67 68.31,166.67 v1(66.02,164.39)
N25587094: length 3
  TOP w0.305: R54.2 84.69,154.74 85.94,155.99 U4.10
N25587194: length 1.4
  BOTTOM w0.254: R208.2 C264.1
N25587240: length 6.2
  BOTTOM w0.254: R236.2 51.31,148.69 51.01,148.39 C283.1 50.41,148.26 49.49,147.34 D12.NP
N25587378: length 2.6
  TOP w0.305: U4.11 86.59,155.8 86.09,155.3 R55.2
N25587545: length 4.5
  TOP w0.102: 84.01,166.57 R16.1
  TOP w0.381: 84.01,166.57 84.16,166.57 85.94,164.78 U4.5
N25594365: length 23
  TOP w0.508: 89.59,138.53 84.57,138.53 84.2,138.16 78.97,138.16 CN3.7 77.7,135.36 CN3.1 ; 89.59,138.53 C153.2 ; 89.59,138.53 89.88,138.24 CN3.12 89.88,135.36 CN3.6
N26013479: length 1.5
  TOP w0.381: C28.2 88.37,169.11 88.27,169.21 R10.1

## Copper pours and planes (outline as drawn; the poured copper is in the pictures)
5VDDM on VCC2 (solid shape): outline of 671 points within 28.68,56.44 171.43,196.39
GND on BOTTOM (solid shape): 46.21,162.23 46.21,158.93 45.83,158.55 43.67,158.55 43.41,158.8 43.41,162.23 43.67,162.48 45.95,162.48
GND on BOTTOM (solid shape): 50.53,139.88 50.53,137.59 50.27,137.34 44.94,137.34 44.3,137.97 44.3,141.66 44.81,142.16 48.24,142.16
GND on BOTTOM (solid shape): 57.73,137.98 57.73,135.72 57.42,135.41 53.08,135.41 52.96,135.54 52.96,137.51 53.64,138.18 57.53,138.18
GND on BOTTOM (solid shape): 70.85,122.99 70.85,120.83 70.59,120.57 69.19,120.57 68.56,121.21 68.56,122.99 68.81,123.24 70.59,123.24
GND on BOTTOM (solid shape): 80.75,174.04 80.75,172.39 80.37,172.01 76.69,172.01 76.31,172.39 76.31,173.91 76.81,174.42 80.37,174.42
GND on BOTTOM (solid shape): 95.1,170.74 95.1,168.33 94.72,167.94 94.47,168.2 92.94,168.2 92.82,168.33 92.82,170.36 93.58,171.12 94.72,171.12
GND on BOTTOM (solid shape): 55.48,127.94 55.48,126.54 55.35,126.42 54.21,126.42 53.7,125.91 53.7,124.76 53.57,124.64 52.56,124.64 52.18,125.02 52.18,127.69 52.56,128.07 55.35,128.07
GND on BOTTOM (solid shape): outline of 105 points within 48.24,105.21 73,137.97
GND on GND1 (solid shape): outline of 1727 points within 15.15,29.19 186.63,200.67
GND on VCC1 (solid shape): outline of 1789 points within 15.15,29.19 186.63,200.67
GND on VCC2 (solid shape): outline of 1390 points within 15.15,29.19 186.63,200.67
GND on GND2 (solid shape): outline of 1751 points within 15.15,29.19 186.63,200.67
VDD12V_POE on BOTTOM (solid shape): 67.29,131.5 67.29,128.45 66.65,127.81 59.67,127.81 59.03,128.45 59.03,130.73 59.29,130.99 62.84,130.99 63.61,131.75 67.04,131.75
VDD13_12 on BOTTOM (solid shape): 51.03,136.7 51.03,133.02 50.84,132.83 44.62,132.83 44.18,133.27 44.18,136.45 44.81,137.08 50.65,137.08
VDD13_12 on VCC1 (solid shape): 88.88,186.25 88.88,173.51 88.65,173.28 81.49,173.28 81.01,173.77 81.01,174.55 80.99,174.65 80.93,174.73 77.76,177.9 77.67,177.96 77.58,177.98 52.05,177.98 51.95,177.96 51.87,177.9 40.31,166.35 40.26,166.26 40.24,166.17 40.24,139.12 40.26,139.02 40.31,138.93 41.71,137.54 41.79,137.48 41.89,137.46 49.66,137.46 50.78,136.34 50.78,129.19 46.1,124.51 29.55,124.51 28.68,125.38 28.68,176.47 33.31,181.1 33.36,181.18 33.38,181.28 33.38,185.85 44.18,185.85 44.27,185.87 44.36,185.92 45.43,186.99 88.14,186.99
VDD_ARM_CAP on VCC2 (solid shape): 128.69,148.31 128.69,144.27 128.55,144.13 123.5,144.13 123.36,144.27 123.36,148.18 123.63,148.45 128.55,148.45
VDDCORE on VCC1 (solid shape): 118.54,158.49 118.63,158.44 118.72,158.42 125.48,158.42 127.94,155.95 128.03,155.9 128.12,155.88 130.56,155.88 131.04,155.39 131.04,148.87 130.23,148.06 130.17,147.98 130.15,147.88 130.15,144.3 129.22,143.37 123.5,143.37 123.36,143.51 123.36,146.02 123.43,146.09 123.47,146.15 123.49,146.23 123.49,147.37 123.47,147.45 123.43,147.51 122.8,148.14 122.74,148.18 122.66,148.2 116.69,148.2 116.62,148.18 116.55,148.14 116.31,147.89 116.26,147.83 116.25,147.75 116.25,147.58 115.92,147.24 111.59,147.24 105.39,153.45 105.39,155.24 105.37,155.34 105.32,155.42 104.12,156.62 104.12,167.84 104.63,168.35 108.61,168.35
VDDPU on VCC1 (solid shape): outline of 93 points within 121.12,132 130.15,142.99
VDDSOC on VCC2 (solid shape): 111.74,176.98 111.74,144.59 110.72,143.57 110.68,143.51 110.66,143.43 110.66,142.67 110.68,142.6 110.72,142.53 111.09,142.16 111.16,142.12 111.23,142.1 112.55,142.1 113,141.65 113.06,141.61 113.14,141.59 122.92,141.59 122.99,141.61 123.06,141.65 123.55,142.15 123.6,142.21 123.61,142.29 123.61,143.61 123.76,143.75 129.06,143.75 129.76,143.05 129.82,143 129.9,142.99 130.2,142.99 130.35,142.85 130.35,139.58 130.27,139.5 129.01,139.5 128.91,139.48 128.83,139.42 128.07,138.66 128.01,138.58 128,138.48 128,134.01 127.64,133.65 113.15,133.65 113.01,133.8 113.01,134.67 112.99,134.77 112.94,134.85 112.56,135.23 112.47,135.29 112.37,135.31 108.42,135.31 104.37,139.35 104.37,176.09 106.26,177.98 110.74,177.98
VDDSOC_CAP on VCC2 (solid shape): 131.87,148.43 131.87,148.13 131.89,148.06 131.93,147.99 132.17,147.75 132.24,147.7 132.31,147.69 132.62,147.69 132.63,147.67 132.63,144.2 132.65,144.12 132.69,144.06 132.94,143.81 133,143.77 133.08,143.75 133.38,143.75 133.52,143.61 133.52,141.78 133.54,141.71 133.58,141.64 134.09,141.13 134.11,141.04 134.17,140.97 136.63,138.5 136.63,134.52 135.64,133.53 131.4,133.53 131.17,133.76 131.17,137.97 131.1,138.15 130.93,138.23 130.73,138.43 130.73,142.93 130.71,143 130.67,143.06 130.42,143.31 130.36,143.35 130.28,143.37 129.98,143.37 129.08,144.27 129.08,148.31 129.22,148.45 129.39,148.45 129.47,148.47 129.53,148.51 129.6,148.58 131.73,148.58
DDR_1V5 on VCC1 (solid shape): 160.51,165.68 160.51,132.11 159.77,131.37 133.69,131.37 132.11,132.95 132.03,133 131.93,133.02 130.81,133.02 130.66,133.16 130.66,137.97 130.64,138.07 130.59,138.15 129.01,139.73 129.01,142.44 130.59,144.01 130.64,144.1 130.66,144.2 130.66,147.77 131.48,148.59 131.53,148.67 131.55,148.77 131.55,158.44 133.69,160.58 137.9,160.58 138,160.6 138.08,160.65 142.27,164.84 142.33,164.93 142.35,165.02 142.35,166.57 143.47,167.69 158.5,167.69
DDR_VREF on VCC2 (solid shape): 148.9,170.43 148.98,170.38 149.08,170.36 156.97,170.36 160.76,166.57 160.76,138.71 156.97,134.92 137.25,134.92 137.14,135.03 137.14,138.61 137.12,138.7 137.07,138.79 134.53,141.33 134.45,141.38 134.36,141.4 133.9,141.86 133.9,143.69 133.89,143.76 133.84,143.83 133.6,144.07 133.53,144.12 133.46,144.13 133.15,144.13 133.01,144.27 133.01,147.75 133,147.83 132.95,147.89 132.83,148.01 132.77,148.05 132.69,148.07 132.39,148.07 132.25,148.21 132.25,150.59 132.95,151.29 133,151.36 133.01,151.43 133.01,152.79 140.88,160.65 140.93,160.73 140.95,160.83 140.95,164.13 140.93,164.23 140.88,164.31 140.06,165.13 140.06,169.09 140.04,169.18 139.99,169.27 137.45,171.81 137.36,171.86 137.27,171.88 131.53,171.88 131.17,172.24 131.17,173.81 131.66,174.29 137.01,174.29 137.11,174.31 137.19,174.37 137.5,174.68 144.65,174.68
ETH_3V3 on VCC1 (solid shape): 162.92,166.57 162.92,130.46 161.54,129.08 131.4,129.08 130.66,129.82 130.66,132.37 130.81,132.51 131.83,132.51 133.4,130.93 133.49,130.88 133.58,130.86 159.87,130.86 159.97,130.88 160.05,130.93 160.94,131.82 161,131.91 161.02,132 161.02,165.79 161,165.88 160.94,165.97 158.78,168.12 158.7,168.18 158.6,168.2 143.36,168.2 143.27,168.18 143.18,168.12 141.91,166.85 141.86,166.77 141.84,166.67 141.84,165.13 137.8,161.09 135.98,161.09 135.87,161.19 135.87,162.88 143.22,170.23 159.26,170.23
ETH_3V3 on VCC2 (solid shape): 130.35,138.91 130.35,138.35 130.36,138.28 130.41,138.21 130.66,137.96 130.66,133.65 130.68,133.56 130.74,133.47 131.12,133.09 131.2,133.04 131.3,133.02 131.83,133.02 132.06,132.79 132.06,130.46 125.86,124.26 99.53,124.26 99.17,124.62 99.17,127.56 99.15,127.66 99.09,127.74 97.7,129.14 97.61,129.19 97.52,129.21 96.73,129.21 96.5,129.44 96.5,130.63 97.24,131.37 106.81,131.37 108.13,130.04 108.21,129.99 108.31,129.97 111.74,129.97 111.84,129.99 111.92,130.04 112.94,131.06 112.99,131.14 113.01,131.24 113.01,133 113.15,133.15 127.74,133.15 127.84,133.17 127.92,133.22 128.43,133.73 128.49,133.81 128.5,133.91 128.5,138.37 129.12,138.99 130.27,138.99
GEN_1V8 on VCC2 (solid shape): 144.51,177.87 144.51,175.54 144.15,175.18 137.39,175.18 137.3,175.16 137.21,175.11 136.91,174.8 131.55,174.8 131.45,174.78 131.37,174.73 130.74,174.09 130.68,174.01 130.66,173.91 130.66,172.14 130.68,172.04 130.74,171.95 131.24,171.45 131.33,171.39 131.42,171.37 134.71,171.37 134.85,171.23 134.85,164.62 130.99,160.76 130.94,160.68 130.92,160.58 130.92,156.24 130.68,156.01 129.37,156.01 126.98,158.4 126.98,159.69 126.96,159.79 126.91,159.87 126.53,160.25 126.44,160.31 126.34,160.32 123.91,160.32 123.68,160.56 123.68,164.41 124.49,165.22 124.55,165.31 124.57,165.4 124.57,166.06 124.8,166.29 125.84,166.29 125.93,166.31 126.02,166.37 126.53,166.87 126.58,166.96 126.6,167.06 126.6,171.75 126.58,171.85 126.53,171.93 125.71,172.75 125.71,173.43 129.83,177.54 129.88,177.63 129.9,177.72 129.9,179.01 130.13,179.25 143.13,179.25
GEN_3V3 on VCC1 (solid shape): outline of 377 points within 33.38,93.01 172.45,197.15
GLH on BOTTOM (solid shape): 75.42,123.11 75.42,121.21 75.16,120.95 73,120.95 72.75,121.21 72.75,123.11 73.07,123.43 75.1,123.43
GLH on IN2 (solid shape): outline of 206 points within 73.13,114.79 93.65,123.62
LVDS_2V5 on VCC2 (solid shape): 139.55,168.98 139.55,165.02 139.57,164.93 139.63,164.84 140.44,164.03 140.44,160.94 132.64,153.14 132.59,153.06 132.57,152.96 132.58,152.87 132.63,152.79 132.63,151.51 131.93,150.81 131.89,150.75 131.87,150.67 131.87,149.1 131.73,148.96 129.84,148.96 129.84,155.17 130.16,155.49 130.17,155.5 130.79,155.5 130.89,155.52 130.97,155.57 131.35,155.95 131.41,156.04 131.42,156.13 131.42,160.47 135.29,164.33 135.34,164.42 135.36,164.52 135.36,171.23 135.5,171.37 137.16,171.37
NVCC_3V3 on VCC1 (solid shape): 122.98,144.37 122.98,143.39 122.84,143.24 121.77,143.24 121.7,143.23 121.63,143.18 120.93,142.48 119.87,142.48 119.79,142.46 119.73,142.42 119.03,141.72 119.02,141.72 118.94,141.77 118.85,141.78 112.35,141.78 111.67,142.47 111.58,142.53 111.49,142.54 110.58,142.54 110.34,142.78 110.34,143.71 110.58,143.94 116.18,143.94 116.27,143.96 116.35,144 121.39,144 121.47,144.02 121.53,144.07 121.98,144.51 122.84,144.51
NVCC_EIM on VCC1 (solid shape): 126.66,140.31 126.66,139.75 126.68,139.67 126.72,139.61 127.3,139.04 127.3,134.37 126.9,133.97 124.52,133.97 124.25,134.24 124.25,140.05 124.9,140.7 126.27,140.7
NVCC_SD1 on VCC2 (solid shape): 116.26,146.05 116.34,145.99 116.44,145.97 116.53,145.99 116.61,146.04 122.84,146.04 122.98,145.89 122.98,144.2 123,144.12 123.04,144.06 123.23,143.86 123.23,142.37 122.84,141.97 113.22,141.97 112.77,142.42 112.7,142.46 112.63,142.48 111.31,142.48 111.04,142.75 111.04,143.35 112.01,144.32 112.18,144.4 112.25,144.58 112.25,147.36 112.26,147.36 112.52,147.62 114.68,147.62
NVCC_SD2 on VCC1 (solid shape): 123.23,142.72 123.23,142.62 122.91,142.3 122.87,142.24 122.85,142.16 122.85,141.86 122.33,141.34 121.65,141.34 121.57,141.32 121.51,141.28 120.75,140.52 120.72,140.48 120.7,140.43 120.65,140.35 120.63,140.26 120.63,136.97 120.42,136.77 109.79,136.77 108.88,137.67 108.88,138.53 109.79,139.43 110.9,139.43 111.04,139.29 111.04,138.86 111.06,138.79 111.1,138.72 111.35,138.48 111.41,138.43 111.49,138.42 116.18,138.42 116.26,138.43 116.32,138.48 117.33,139.48 117.38,139.55 117.39,139.62 117.39,141.07 117.6,141.27 118.85,141.27 118.94,141.29 119.02,141.34 119.11,141.34 119.18,141.35 119.25,141.4 119.95,142.1 121.01,142.1 121.09,142.12 121.15,142.16 121.85,142.86 123.09,142.86
PMU3V on VCC1 (solid shape): 131.12,177.29 131.2,177.23 131.3,177.22 135.62,177.22 135.71,177.23 135.8,177.29 137.12,178.61 139.7,178.61 140.19,178.12 140.19,173.89 132.46,166.17 120.74,166.17 118.22,168.69 118.22,174.93 118.2,175.03 118.14,175.11 117.51,175.74 117.43,175.8 117.33,175.82 105.39,175.82 105.29,175.8 105.21,175.74 100.71,171.25 98,171.25 97.64,171.61 97.64,186.76 98.51,187.63 120.78,187.63
POE_PRI_SW_NODE on TOP (solid shape): 60.69,167.18 60.69,160.45 59.92,159.69 56.37,159.69 55.73,160.32 55.73,165.53 57.51,167.31 60.56,167.31
POE_PRI_SW_NODE on BOTTOM (solid shape): 61.45,161.85 61.45,154.86 61.19,154.61 60.3,154.61 60.05,154.86 60.05,156.77 59.03,157.78 56.49,157.78 55.99,158.29 55.99,162.1 56.24,162.36 60.94,162.36
POE_RTN on BOTTOM (solid shape): 51.92,161.59 51.92,159.69 50.91,158.67 49,158.67 48.75,158.93 48.75,162.1 49,162.36 51.16,162.36
POE_RTN on BOTTOM (solid shape): 74.78,148.51 74.78,146.86 74.4,146.48 71.86,146.48 71.48,146.86 71.48,148.64 71.61,148.77 74.53,148.77
POE_RTN on BOTTOM (solid shape): 66.4,157.66 66.4,154.86 66.15,154.61 65.26,154.61 65,154.86 65,157.66 65.13,157.78 66.27,157.78
POE_RTN on BOTTOM (solid shape): 78.21,157.15 78.21,153.47 77.32,152.58 75.29,152.58 74.66,153.21 74.66,157.78 75.04,158.17 77.2,158.17
POE_RTN on BOTTOM (solid shape): 72.37,167.31 72.37,164.9 71.48,164.01 69.58,164.01 68.81,164.77 66.4,164.77 66.27,164.9 66.27,167.44 66.4,167.56 72.12,167.56
POE_RTN on GND2 (solid shape): 90.66,169.55 90.66,164.39 90.74,164 90.96,163.67 91.29,163.33 91.29,159.91 91.26,159.89 91.24,159.87 90.93,159.56 87.48,159.56 87.39,159.54 87.3,159.49 86.79,158.98 86.74,158.9 86.72,158.8 86.72,153.95 86.41,153.65 86.36,153.56 86.34,153.47 86.34,151.74 86.08,151.49 86.06,151.46 86.04,151.43 77.32,151.43 77.23,151.42 77.14,151.36 74.98,149.2 74.93,149.12 74.91,149.02 74.91,146.67 74.47,146.23 71.41,146.23 70.34,147.3 70.34,153.59 70.32,153.69 70.26,153.77 69.63,154.41 69.55,154.46 69.45,154.48 69.17,154.48 69.17,154.49 69.04,154.58 68.89,154.61 55.77,154.61 54.93,155.46 54.6,155.68 54.21,155.75 49.17,155.75 48.49,156.43 48.49,162.06 56.28,169.85 81.01,169.85 81.39,169.93 81.72,170.15 82.82,171.25 88.97,171.25
POE_RTN on TOP: outline of 88 points within 48.49,146.48 91.29,169.21
POE_RTN on IN2: 78.41,157.33 81.45,160.37 86.59,160.37 87.05,160.83 86.59,161.29 81.07,161.29 77.2,157.42 77.2,152.9 74.65,150.36 74.56,149.84 75.15,149.51 75.13,149.37 74.91,149.15 74.91,146.74 74.4,146.23 71.48,146.23 70.34,147.37 70.34,153.72 69.58,154.48 55.86,154.48 54.59,155.75 49.13,155.75 48.49,156.39 48.49,162.1 56.24,169.85 56.6,169.85 56.71,169.79 56.72,169.67 57.13,169.01 57.54,169.67 57.55,169.79 57.66,169.85 81.39,169.85 82.78,171.25 89.01,171.25 90.66,169.6 90.66,163.88 91.29,163.25 91.29,152.98 91.23,152.87 91.11,152.86 90.54,152.72 90.58,152.13 90.46,151.89 90.5,151.62 90.49,151.49 90.39,151.43 79.35,151.43 78.41,152.38
POE_VDD on TOP (solid shape): 84.82,157.86 84.82,156.18 84.79,156.16 84.56,156.16 84.56,155.37 84.43,155.24 84.16,155.24 83.95,155.04 83.95,154.25 84.36,153.85 84.82,153.85 85.07,153.59 85.07,151.82 84.77,151.51 80.47,151.51 80.12,151.87 80.12,157.53 80.62,158.04 84.64,158.04
POE_VDD on BOTTOM: 77.7,166.93 77.96,167.18 82.15,167.18 82.53,166.8 82.53,162.23 86.85,157.91 86.85,153.97 86.59,153.72 86.59,152.45 86.52,152.21 86.58,151.96 86.59,151.94 86.59,151.82 86.18,151.4 80.91,151.4 79.23,153.09 79.23,157.15 77.7,158.67
POE_VDD_CN on TOP (solid shape): 83.55,150.16 83.55,146.99 83.29,146.74 75.8,146.74 75.54,146.99 75.54,148.77 77.13,150.35 83.36,150.35
POE_VDD_CN on BOTTOM (solid shape): 77.45,148.64 77.45,146.99 77.2,146.74 75.67,146.74 75.42,146.99 75.42,148.89 75.67,149.15 76.94,149.15
POE_VDD_CN on BOTTOM (solid shape): 83.55,148.77 83.55,146.99 83.29,146.74 80.24,146.74 80.12,146.86 80.12,148.89 80.37,149.15 83.16,149.15
POE_VSS on TOP (solid shape): 84.82,163.88 84.82,162.23 83.67,162.23 83.55,162.36 83.55,163.88 83.67,164.01 84.69,164.01
POE_VSS on GND1 (solid shape): 84.69,163.77 84.69,160.2 84.71,160.1 84.76,160.02 86.72,158.06 86.72,153.21 86.74,153.11 86.79,153.03 87.56,152.27 87.64,152.22 87.74,152.2 91.06,152.2 91.29,151.96 91.29,150.08 90.87,149.66 88.1,149.66 86.39,151.36 86.31,151.42 86.21,151.43 84.92,151.43 84.69,151.67 84.69,157.28 84.67,157.37 84.62,157.46 82.15,159.92 82.15,163.77 82.51,164.13 84.33,164.13
POE_VSS on BOTTOM: 90.2,157.73 90.21,157.71 90.33,157.46 90.58,157.33 90.61,157.33 91.17,156.77 91.17,153.91 91.12,153.81 91.01,153.79 90.45,153.34 91.01,152.89 91.12,152.87 91.17,152.77 91.17,149.53 90.53,148.89 87.99,148.89 87.61,149.28 87.61,150.8 86.72,151.69 86.72,153.09 87.36,153.72 87.36,158.55 87.48,158.67 89.26,158.67
POE_VSS_CN on BOTTOM (solid shape): 86.47,150.93 86.47,147.37 86.21,147.12 84.82,147.12 84.56,147.37 84.56,149.02 84.05,149.53 80.24,149.53 79.61,148.89 79.61,147.24 79.35,146.99 78.21,146.99 77.96,147.24 77.96,150.16 78.85,151.05 86.34,151.05
SATA_VP on VCC1 (solid shape): 122.98,145.77 122.98,145.04 122.84,144.89 121.9,144.89 121.82,144.88 121.76,144.83 121.31,144.39 116.9,144.39 116.63,144.66 116.63,145.64 116.77,145.78 121.01,145.78 121.09,145.8 121.15,145.84 121.34,146.04 122.71,146.04
SATA_VPH on VCC1 (solid shape): 123.11,147.29 123.11,146.69 122.84,146.42 121.26,146.42 121.19,146.4 121.13,146.36 120.93,146.16 116.77,146.16 116.63,146.31 116.63,147.67 116.77,147.81 122.58,147.81
VSNVS_3V0 on VCC2 (solid shape): 129.39,180.92 129.39,177.83 125.28,173.71 125.22,173.63 125.2,173.53 125.2,172.64 125.22,172.55 125.28,172.46 126.09,171.65 126.09,167.16 125.73,166.8 124.69,166.8 124.6,166.78 124.51,166.73 124.13,166.35 124.08,166.26 124.06,166.17 124.06,165.51 123.24,164.7 123.19,164.61 123.17,164.52 123.17,160.45 123.19,160.35 123.24,160.27 123.62,159.89 123.71,159.84 123.8,159.82 126.24,159.82 126.47,159.58 126.47,158.29 126.49,158.19 126.55,158.11 129.09,155.57 129.16,155.52 129.25,155.5 129.46,155.29 129.46,148.97 129.31,148.83 123.55,148.83 123.47,148.81 123.41,148.77 123.04,148.4 123,148.34 122.98,148.26 122.98,146.56 122.84,146.42 116.61,146.42 114.97,148.06 114.89,148.11 114.79,148.13 112.64,148.13 112.64,148.14 112.26,148.52 112.25,148.53 112.25,177.09 112.23,177.19 112.17,177.27 111.03,178.41 110.95,178.47 110.85,178.49 106.15,178.49 106.05,178.47 105.97,178.41 103.94,176.38 103.88,176.3 103.87,176.2 103.87,151.45 103.86,151.44 103.6,151.18 102.7,151.18 102.6,151.29 102.6,152.45 102.58,152.55 102.52,152.63 99.04,156.11 99.04,176.86 104.73,182.42 127.89,182.42
N25585918 on BOTTOM (solid shape): 65.51,166.29 65.51,164.52 65.38,164.39 61.7,164.39 61.07,163.75 58.65,163.75 58.4,164.01 58.4,165.91 59.16,166.67 65.13,166.67
N25586882 on BOTTOM (solid shape): 70.21,140.89 70.21,133.53 69.96,133.27 64.37,133.27 63.48,134.16 63.48,136.96 64.5,137.97 64.5,140.77 65,141.27 69.83,141.27
N25586910 on TOP (solid shape): 67.67,165.28 67.67,162.74 67.29,162.36 63.35,162.36 62.97,162.74 62.97,165.66 63.35,166.04 66.91,166.04
N25587015 on BOTTOM (solid shape): 63.99,140.89 63.99,138.99 61.83,136.83 61.83,132.51 61.45,132.13 58.91,132.13 58.4,132.64 58.4,138.1 59.54,139.24 59.54,140.89 59.92,141.27 63.61,141.27
N25587065 on BOTTOM (solid shape): 80.24,169.47 80.24,167.94 79.74,167.44 77.32,167.44 76.81,166.93 76.81,159.45 76.13,158.77 65.48,158.77 63.86,157.15 63.86,154.74 63.61,154.48 62.97,154.48 62.59,154.86 62.59,156.51 61.83,157.28 61.83,163.25 62.21,163.63 72.12,163.63 72.75,164.26 72.75,169.09 73.39,169.72 79.99,169.72
N25600625 on BOTTOM (solid shape): 63.61,127.05 63.61,119.3 62.46,118.16 59.54,118.16 58.02,119.68 58.02,126.92 58.53,127.43 63.23,127.43
N25600639 on BOTTOM (solid shape): 53.57,124 53.57,120.95 52.56,119.94 48.62,119.94 47.99,120.57 47.99,123.88 48.37,124.26 53.32,124.26
N25600655 on BOTTOM (solid shape): 57.26,131.11 57.26,128.7 57,128.45 52.56,128.45 51.92,127.81 51.92,125.27 51.8,125.15 48.24,125.15 47.99,125.4 47.99,130.73 49,131.75 56.62,131.75
N25600703 on BOTTOM (solid shape): 57.45,125.84 57.45,122.54 57.13,122.22 54.59,122.22 53.95,122.86 53.95,125.78 54.34,126.16 57.13,126.16
N25856521 on BOTTOM (solid shape): 56.75,134.67 56.75,132.51 56.49,132.26 53.57,132.26 53.19,132.64 53.19,134.8 53.45,135.05 56.37,135.05

Small or netless copper shapes (teardrops, artwork), in the pictures only: 2 on IN1

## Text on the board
BOTTOM: 8
Ref Des/Silkscreen Bottom: A
Board Geometry/Outline: Project Name : | DOC  : | LAYER: | Release Date : | Version num. : | 2015/11/24 | 0.1
TOP: 1
Ref Des/Silkscreen Top: Tinto MB 1.6mm 8 Layer Ver:0.1    2015/10/29 | TINTO M/B VER:0.1 | 2015/11/05 | 50-70196-30
GND1: 2
IN1: IN1(L3) | 3
VCC1: VCC1(L4) | 4
VCC2: VCC2(L5) | 5
IN2: IN2(L6) | 6
GND2: 7
DIMENSION: PASTEMASK_TOP
DISPLAY_BOTTOM: PASTEMASK_BOT
User.5: VDD_ARM_CAP | NVCC_SD1 | VSNVS_3V0 | LVDS_2V5 | GEN_1V8 | ETH_3V3 | VDDSOC | DDR_VREF | 5VDDM | GND | VDDSOC_CAP
User.6: VDD13_12 | SATA_VPH | SATA_VP | NVCC_SD2 | GND | VDDCORE | NVCC_3V3 | PMU3V | VDDPU | DDR_1V5 | ETH_3V3 | GEN_3V3 | NVCC_EIM
User.7: POE_VSS | GND
User.8: POE_RTN | GND
User.26: FIGURE | SIZE | 10.0 | 31.5 | 35.43 | 39.37 | 40.0 | 51.18 | 59.06 | 129.92 | 145.67 | 224.41 | 255.91 | 62.99 | 127.95 | 160.0 | 39.37x62.99 | 31.5x78.74 | 118.11x31.5 | DRILL CHART: TOP to BOTTOM | ALL UNITS ARE IN MILS | PLATED | NON-PLATED | QTY | 3357 | 4 | 10 | 8 | 9 | 2 | 1 | 6 | 7
User.44: XY-Create nettxt:Oct 05 18:27:32 2015 | XY-Create plane:Oct 05 18:29:08 2015 | create nettxt:Oct 05 18:27:32 2015 | create plane:Oct 05 18:29:08 2015 | Excess check:Oct 28 17:58:09 2015 | GNDVIA_CHECK:Oct 28 17:43:17 2015 | PadStack_Check:Oct 28 13:05:25 2015 | XY-Check acute:Oct 28 14:47:23 2015 | XY-Check cline width:Oct 28 18:02:12 2015 | XY-Check rotation:Oct 28 18:05:33 2015 | XY-Check txt overlap:Oct 28 18:30:26 2015 | XY-Check txt:Oct 28 18:34:52 2015 | XY-Create nettxt:Nov 24 16:38:23 2015 | XY-Create plane:Nov 24 16:56:51 2015 | XY-Dxf to pin check:Oct 28 14:38:41 2015 | XY-Excess check:Oct 28 17:58:09 2015 | XY-GNDVIA_CHECK:Oct 28 17:43:17 2015 | XY-Mask check:Oct 29 11:16:50 2015 | XY-PadStack_Check:Oct 28 13:05:25 2015 | XY-Plane net check:Oct 29 08:39:59 2015 | XY-bbvia check:Oct 28 17:18:51 2015 | XY-shape min check:Oct 28 18:53:26 2015 | XY-shape pin check:Oct 28 17:48:13 2015 | XY-via check:Oct 28 14:59:37 2015 | bbvia check:Oct 28 17:18:51 2015 | check acute:Oct 28 14:47:23 2015 | check cline width:Oct 28 18:02:12 2015 | check rotation:Oct 28 18:05:33 2015 | check txt overlap:Oct 28 18:30:26 2015 | check txt:Oct 28 18:34:52 2015 | create nettxt:Nov 24 16:38:23 2015 | create plane:Nov 24 16:56:51 2015 | dxf to pin check:Oct 28 14:38:41 2015 | plane net check:Oct 29 08:39:59 2015 | shape min check:Oct 28 18:53:26 2015 | shape pin check:Oct 28 17:48:13 2015 | via check:Oct 28 14:59:37 2015
